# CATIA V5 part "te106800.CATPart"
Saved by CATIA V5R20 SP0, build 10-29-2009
Part number: 1
Definition: NONE
Nomenclature: 1
Source: Unknown
Description: PART-1-DESC
Bounding box of the stored display mesh (mm): x 0 to 800, y -5 to 5, z -5 to 5
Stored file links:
  C:\Users\Utente\Desktop\IO LAVORO\3D X SITO CF\CUMSA\3D files TE\te106800.CATPart
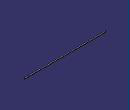
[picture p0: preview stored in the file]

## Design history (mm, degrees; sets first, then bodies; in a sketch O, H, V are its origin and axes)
Body1 "1" (main body)
  Solid1: solid without history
